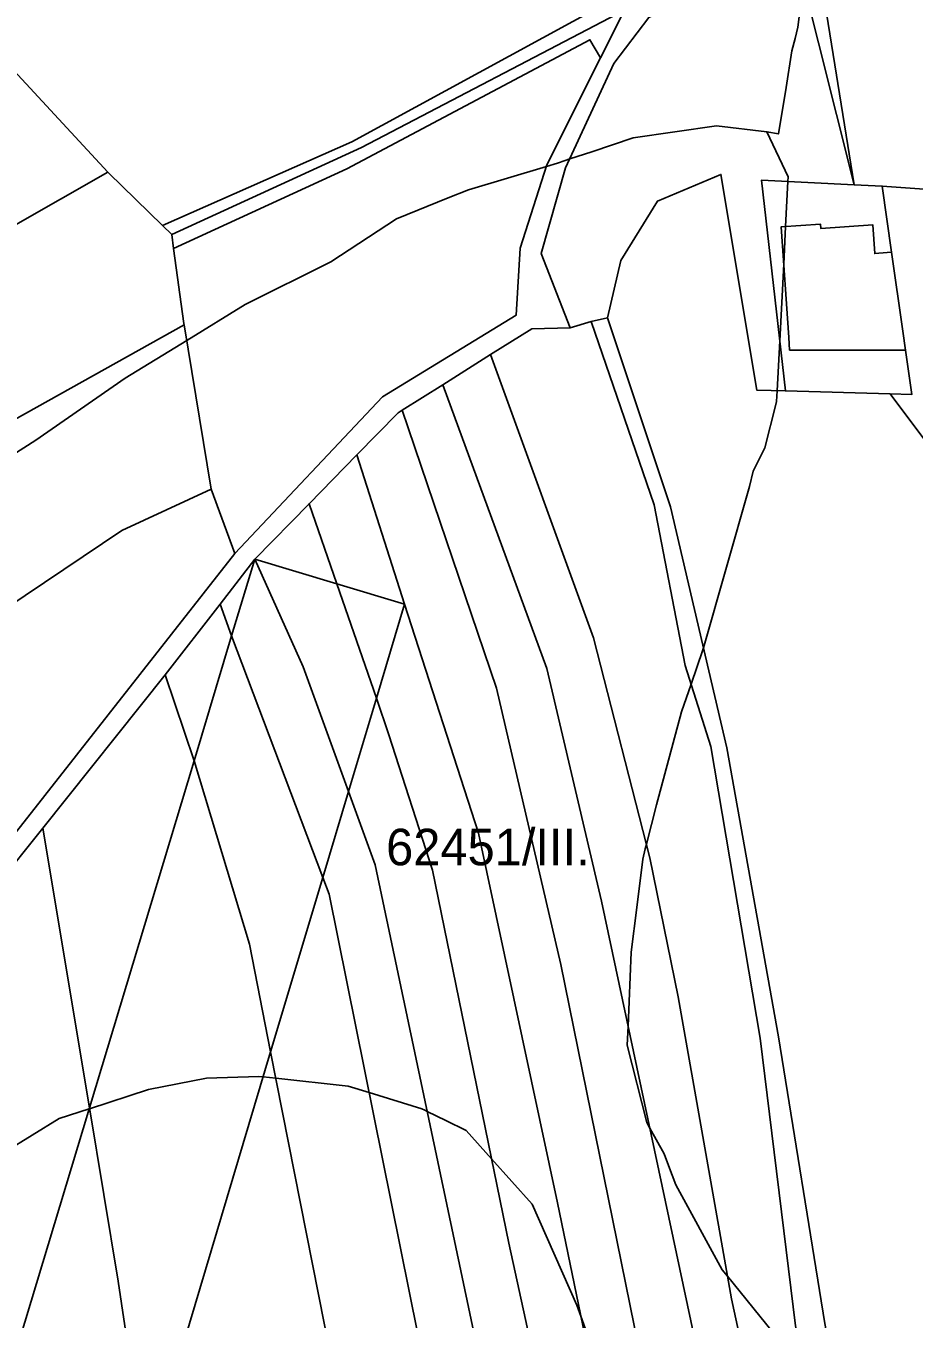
# Model space of a CAD drawing. Extents: x -502026 to -497664, y -1143484 to -1138019.
# Drawn here: x -499718.6 to -499523.9, y -1138993.9 to -1138710.6 of the extents above; entities that cross this region are included whole.
import ezdxf

# ---------------------------------------------------------------- set-up
doc = ezdxf.new("R2010")
doc.units = 0
for name, color, linetype in [('25', 7, 'Continuous'), ('31', 7, 'Continuous'), ('37', 7, 'Continuous'), ('43', 7, 'Continuous'), ('55', 7, 'Continuous'), ('62', 7, 'Continuous'), ('7', 7, 'Continuous')]:
    doc.layers.add(name, color=color, linetype=linetype)

msp = doc.modelspace()

# ---------------------------------------------------------------- linework, layer by layer
at = {"layer": '25'}
for points in [[(-499537.01, -1138745.37), (-499530.87, -1138745.67), (-499528.82, -1138760.16), (-499531.63, -1138760.38), (-499532.54, -1138760.45), (-499532.98, -1138754.15), (-499544.35, -1138754.93), (-499544.41, -1138754.03), (-499553.04, -1138754.62), (-499551.38, -1138778.83), (-499551.19, -1138781.59), (-499525.8, -1138781.59), (-499524.4, -1138791.35), (-499529.18, -1138791.22), (-499552.1, -1138790.55), (-499557.37, -1138744.4)], [(-499513.48, -1138746.91), (-499511.89, -1138808.1), (-499511.73, -1138814.39), (-499529.18, -1138791.22), (-499524.4, -1138791.35), (-499525.8, -1138781.59), (-499526.38, -1138777.45), (-499528.82, -1138760.16), (-499530.87, -1138745.67)]]:
    msp.add_lwpolyline(points, close=True, dxfattribs=at)
at = {"layer": '31'}
msp.add_lwpolyline([(-499537.01, -1138745.37), (-499557.37, -1138744.4), (-499552.1, -1138790.55), (-499558.38, -1138790.37), (-499566.24, -1138743.1), (-499580.14, -1138748.95), (-499588.16, -1138761.99), (-499591.11, -1138774.54), (-499594.7, -1138775.32), (-499599.24, -1138776.76), (-499605.61, -1138760.41), (-499600.27, -1138741.69), (-499589.7, -1138718.79), (-499582.04, -1138708.7), (-499568.17, -1138701.36), (-499548.75, -1138698.77)], close=True, dxfattribs=at)
at = {"layer": '37'}
msp.add_lwpolyline([(-499513.48, -1138746.91), (-499530.87, -1138745.67), (-499537.01, -1138745.37), (-499544.51, -1138699.06), (-499543.1, -1138676.2), (-499528.49, -1138637.04), (-499524.27, -1138622.83), (-499521.46, -1138603.68)], dxfattribs=at)
for points in [[(-499584.72, -1138701.93), (-499647.14, -1138735.95), (-499688.61, -1138754.3), (-499700.38, -1138742.85), (-499700.56, -1138742.65), (-499729.36, -1138711.56), (-499750.17, -1138715.52), (-499792.14, -1138739.41), (-499812.14, -1138754.89), (-499835.52, -1138777.51), (-499839.65, -1138763.23), (-499841.22, -1138736.39), (-499828.03, -1138721.09), (-499812.98, -1138708.74), (-499778.38, -1138690.2), (-499715.47, -1138666.65), (-499697.07, -1138662.14), (-499624.19, -1138623.47), (-499605.59, -1138653.48), (-499597.17, -1138655.53), (-499535.12, -1138622.58), (-499555.94, -1138687.68), (-499558.61, -1138690.15), (-499573.23, -1138697.97)], [(-499587.35, -1138707.16), (-499644.97, -1138737.18), (-499686.59, -1138756.26), (-499688.61, -1138754.3), (-499647.14, -1138735.95), (-499584.72, -1138701.93)], [(-499592.6, -1138717.6), (-499594.93, -1138713.6), (-499648.25, -1138741.88), (-499686.17, -1138759.35), (-499686.59, -1138756.26), (-499644.97, -1138737.18), (-499587.35, -1138707.16)], [(-499700.56, -1138742.65), (-499742.16, -1138766.28), (-499759.69, -1138777.83), (-499794.21, -1138803.47), (-499825.87, -1138829.77), (-499828.42, -1138802.06), (-499835.52, -1138777.51), (-499812.14, -1138754.89), (-499792.14, -1138739.41), (-499750.17, -1138715.52), (-499729.36, -1138711.56)], [(-499592.6, -1138717.6), (-499604.38, -1138741.01), (-499610.25, -1138759.27), (-499611.14, -1138773.96), (-499640.38, -1138791.84), (-499672.73, -1138826.19), (-499677.97, -1138812.1), (-499683.87, -1138776.05), (-499683.91, -1138775.8), (-499686.17, -1138759.35), (-499648.25, -1138741.88), (-499594.93, -1138713.6)], [(-499688.61, -1138754.3), (-499686.59, -1138756.26), (-499686.17, -1138759.35), (-499683.91, -1138775.8), (-499683.87, -1138776.05), (-499741.05, -1138807.99), (-499788.02, -1138846.17), (-499817.14, -1138873.87), (-499819.87, -1138875.19), (-499825.87, -1138829.77), (-499794.21, -1138803.47), (-499759.69, -1138777.83), (-499742.16, -1138766.28), (-499700.56, -1138742.65), (-499700.38, -1138742.85)], [(-499552.1, -1138790.55), (-499529.18, -1138791.22), (-499511.73, -1138814.39), (-499465.58, -1138874.76), (-499448.8, -1138941.59), (-499481.51, -1138993.07), (-499490.65, -1139028.16), (-499509.08, -1139023.11), (-499518.14, -1139024.19), (-499536.05, -1139033.29), (-499543.48, -1138994.87), (-499553.65, -1138932.11), (-499564.96, -1138868.79), (-499577.25, -1138815.93), (-499591.11, -1138774.54), (-499588.16, -1138761.99), (-499580.14, -1138748.95), (-499566.24, -1138743.1), (-499558.38, -1138790.37)], [(-499677.97, -1138812.1), (-499697.49, -1138821.17), (-499735.75, -1138846.76), (-499768.66, -1138874.79), (-499818.19, -1138913.08), (-499818.08, -1138888.78), (-499819.87, -1138875.19), (-499817.14, -1138873.87), (-499788.02, -1138846.17), (-499741.05, -1138807.99), (-499683.87, -1138776.05)], [(-499672.73, -1138826.19), (-499728.38, -1138896.85), (-499761.65, -1138926.83), (-499778.12, -1138948.42), (-499808.88, -1138958.63), (-499811.95, -1138942.47), (-499818.21, -1138917.28), (-499818.19, -1138913.08), (-499768.66, -1138874.79), (-499735.75, -1138846.76), (-499697.49, -1138821.17), (-499677.97, -1138812.1)], [(-499647.86, -1138878.32), (-499653.5, -1138897.19), (-499673.46, -1138844.21), (-499668.41, -1138827.44), (-499657.82, -1138850.99)], [(-499650.43, -1138832.83), (-499641.75, -1138857.88), (-499647.86, -1138878.32), (-499657.82, -1138850.99), (-499668.41, -1138827.44)], [(-499635.6, -1138837.28), (-499641.75, -1138857.88), (-499650.43, -1138832.83)], [(-499653.5, -1138897.19), (-499664.91, -1138935.38), (-499669.55, -1138911.75), (-499681.68, -1138871.58), (-499673.46, -1138844.21)], [(-499664.91, -1138935.38), (-499692.22, -1139026.74), (-499698.3, -1138985.62), (-499704.64, -1138947.61), (-499681.68, -1138871.58), (-499669.55, -1138911.75)], [(-499692.22, -1139026.74), (-499706.34, -1139073.94), (-499740.09, -1139074.1), (-499740.7, -1139066.99), (-499704.64, -1138947.61), (-499698.3, -1138985.62)]]:
    msp.add_lwpolyline(points, close=True, dxfattribs=at)
at = {"layer": '43'}
msp.add_lwpolyline([(-499537.01, -1138745.37), (-499548.75, -1138698.77), (-499546.8, -1138675.05), (-499544.76, -1138664.32), (-499536.74, -1138644.34), (-499529, -1138621.3), (-499527.08, -1138606.23), (-499515.85, -1138575.58), (-499509.34, -1138543.14), (-499505.39, -1138478.58), (-499500.91, -1138476.52), (-499503.34, -1138544.42), (-499509.59, -1138576.6), (-499521.46, -1138603.68), (-499524.27, -1138622.83), (-499528.49, -1138637.04), (-499543.1, -1138676.2), (-499544.51, -1138699.06)], close=True, dxfattribs=at)
at = {"layer": '55'}
for points in [[(-499728.38, -1138896.85), (-499672.73, -1138826.19), (-499640.38, -1138791.84), (-499611.14, -1138773.96), (-499610.25, -1138759.27), (-499604.38, -1138741.01), (-499592.6, -1138717.6), (-499587.35, -1138707.16)], [(-499582.04, -1138708.7), (-499589.7, -1138718.79), (-499600.27, -1138741.69), (-499605.61, -1138760.41), (-499599.24, -1138776.76), (-499607.64, -1138776.92), (-499616.74, -1138782.59), (-499627.2, -1138789.19), (-499636.08, -1138794.8), (-499637, -1138795.38), (-499646, -1138804.57), (-499656.5, -1138815.29), (-499668.41, -1138827.44), (-499675.99, -1138837.31), (-499688.06, -1138852.74), (-499714.87, -1138886.33), (-499725.1, -1138899.04)]]:
    msp.add_lwpolyline(points, dxfattribs=at)
for points in [[(-499528.82, -1138760.16), (-499526.38, -1138777.45), (-499525.8, -1138781.59), (-499551.19, -1138781.59), (-499551.38, -1138778.83), (-499553.04, -1138754.62), (-499544.41, -1138754.03), (-499544.35, -1138754.93), (-499532.98, -1138754.15), (-499532.54, -1138760.45), (-499531.63, -1138760.38)], [(-499536.05, -1139033.29), (-499534.62, -1139040.71), (-499533.7, -1139045.48), (-499567.38, -1139073.53), (-499568.33, -1139069.19), (-499558.8, -1139060.19), (-499550.32, -1139052.19), (-499539.22, -1139041.71), (-499549.88, -1138995.4), (-499557.61, -1138932.35), (-499568.42, -1138868.46), (-499574.1, -1138850.74), (-499580.84, -1138815.48), (-499594.7, -1138775.32), (-499591.11, -1138774.54), (-499577.25, -1138815.93), (-499564.96, -1138868.79), (-499553.65, -1138932.11), (-499543.48, -1138994.87)]]:
    msp.add_lwpolyline(points, close=True, dxfattribs=at)
at = {"layer": '62'}
for points in [[(-499548.53, -1138704), (-499549.37, -1138710.87), (-499549.99, -1138713.35), (-499550.66, -1138716), (-499551.97, -1138724.08), (-499553.62, -1138734.25), (-499556.16, -1138733.75), (-499567.22, -1138732.5), (-499585.5, -1138735.12), (-499594.55, -1138738.13), (-499599.36, -1138739.73), (-499600.39, -1138740.07), (-499602.06, -1138740.62), (-499604.49, -1138741.35), (-499621.59, -1138746.5), (-499625.98, -1138748.28), (-499637.31, -1138752.87), (-499651.75, -1138762.25), (-499670.47, -1138771.62), (-499683.31, -1138779.48), (-499696.81, -1138787.75), (-499716.34, -1138801.37), (-499743.09, -1138818.37)], [(-499554.91, -1138996.75), (-499564.83, -1138984.49), (-499565.94, -1138983.12), (-499576.12, -1138964.5), (-499577.73, -1138960.28), (-499578.69, -1138957.75), (-499581.82, -1138952.1), (-499582.5, -1138950.87), (-499586.75, -1138933.87), (-499586.58, -1138929.76), (-499585.91, -1138913.5), (-499584.7, -1138903.77), (-499583.37, -1138893.12), (-499582.81, -1138890.9), (-499582.55, -1138889.85), (-499580.37, -1138881.25), (-499574.87, -1138860.87), (-499572.79, -1138854.82), (-499570.19, -1138847.25), (-499570.07, -1138846.83), (-499560, -1138811.5), (-499559.16, -1138808.12), (-499557.57, -1138804.95), (-499556.59, -1138803), (-499554.19, -1138793.5), (-499554.03, -1138792.87), (-499553.91, -1138790.5), (-499553.35, -1138779.61), (-499552.48, -1138762.75), (-499552.06, -1138754.55), (-499551.55, -1138744.68), (-499551.5, -1138743.62), (-499556.16, -1138733.75), (-499553.62, -1138734.25), (-499551.97, -1138724.08), (-499550.66, -1138716), (-499549.99, -1138713.35), (-499549.37, -1138710.87), (-499548.53, -1138704)], [(-499743.09, -1138818.37), (-499716.34, -1138801.37), (-499696.81, -1138787.75), (-499683.31, -1138779.48), (-499670.47, -1138771.62), (-499651.75, -1138762.25), (-499637.31, -1138752.87), (-499625.98, -1138748.28), (-499621.59, -1138746.5), (-499604.49, -1138741.35), (-499602.06, -1138740.62), (-499600.39, -1138740.07), (-499599.36, -1138739.73), (-499594.55, -1138738.13), (-499585.5, -1138735.12), (-499567.22, -1138732.5), (-499556.16, -1138733.75), (-499551.5, -1138743.62), (-499551.55, -1138744.68), (-499552.06, -1138754.55), (-499552.48, -1138762.75), (-499553.35, -1138779.61), (-499553.91, -1138790.5), (-499554.03, -1138792.87), (-499554.19, -1138793.5), (-499556.59, -1138803), (-499557.57, -1138804.95), (-499559.16, -1138808.12), (-499560, -1138811.5), (-499570.07, -1138846.83), (-499570.19, -1138847.25), (-499572.79, -1138854.82), (-499574.87, -1138860.87), (-499580.37, -1138881.25), (-499582.55, -1138889.85), (-499582.81, -1138890.9), (-499583.37, -1138893.12), (-499584.7, -1138903.77), (-499585.91, -1138913.5), (-499586.58, -1138929.76), (-499586.75, -1138933.87), (-499582.5, -1138950.87), (-499581.82, -1138952.1), (-499578.69, -1138957.75), (-499577.73, -1138960.28), (-499576.12, -1138964.5), (-499565.94, -1138983.12), (-499564.83, -1138984.49), (-499554.91, -1138996.75)], [(-499723.12, -1138957.25), (-499711.25, -1138950), (-499704.72, -1138947.87), (-499704.6, -1138947.83), (-499691.69, -1138943.62), (-499678.97, -1138941.12), (-499667.47, -1138940.75), (-499666.55, -1138940.85), (-499663.77, -1138941.15), (-499647.94, -1138942.87), (-499643.35, -1138944.29), (-499631.78, -1138947.87), (-499631.16, -1138948.17), (-499630.61, -1138948.45), (-499626.54, -1138950.43), (-499622.03, -1138952.62), (-499616.51, -1138958.79), (-499607.59, -1138968.75), (-499597.81, -1138990.87), (-499596.96, -1138993.25), (-499583.78, -1139029.87)], [(-499583.78, -1139029.87), (-499596.96, -1138993.25), (-499597.81, -1138990.87), (-499607.59, -1138968.75), (-499616.51, -1138958.79), (-499622.03, -1138952.62), (-499626.54, -1138950.43), (-499630.61, -1138948.45), (-499631.16, -1138948.17), (-499631.78, -1138947.87), (-499643.35, -1138944.29), (-499647.94, -1138942.87), (-499663.77, -1138941.15), (-499666.55, -1138940.85), (-499667.47, -1138940.75), (-499678.97, -1138941.12), (-499691.69, -1138943.62), (-499704.6, -1138947.83), (-499704.72, -1138947.87), (-499711.25, -1138950), (-499723.12, -1138957.25)]]:
    msp.add_lwpolyline(points, dxfattribs=at)
at = {"layer": '7'}
for points in [[(-499550.32, -1139052.19), (-499563.95, -1138989.48), (-499575.62, -1138923.31), (-499581.78, -1138892.84), (-499594.17, -1138844.68), (-499616.74, -1138782.59), (-499607.64, -1138776.92), (-499599.24, -1138776.76), (-499594.7, -1138775.32), (-499580.84, -1138815.48), (-499574.1, -1138850.74), (-499568.42, -1138868.46), (-499557.61, -1138932.35), (-499549.88, -1138995.4), (-499539.22, -1139041.71)], [(-499550.32, -1139052.19), (-499558.8, -1139060.19), (-499592.41, -1138902.38), (-499604.4, -1138851.39), (-499627.2, -1138789.19), (-499616.74, -1138782.59), (-499594.17, -1138844.68), (-499581.78, -1138892.84), (-499575.62, -1138923.31), (-499563.95, -1138989.48)], [(-499558.8, -1139060.19), (-499568.33, -1139069.19), (-499570.98, -1139071.69), (-499581.43, -1139014.02), (-499601.29, -1138916.25), (-499615.44, -1138855.68), (-499636.08, -1138794.8), (-499627.2, -1138789.19), (-499604.4, -1138851.39), (-499592.41, -1138902.38)], [(-499570.98, -1139071.69), (-499575.22, -1139075.69), (-499579.95, -1139075.59), (-499602.08, -1138968.45), (-499619.35, -1138887.46), (-499635.6, -1138837.28), (-499646, -1138804.57), (-499637, -1138795.38), (-499636.08, -1138794.8), (-499615.44, -1138855.68), (-499601.29, -1138916.25), (-499581.43, -1139014.02)], [(-499635.6, -1138837.28), (-499650.43, -1138832.83), (-499656.5, -1138815.29), (-499646, -1138804.57)], [(-499650.43, -1138832.83), (-499668.41, -1138827.44), (-499656.5, -1138815.29)], [(-499673.46, -1138844.21), (-499675.99, -1138837.31), (-499668.41, -1138827.44)], [(-499673.46, -1138844.21), (-499681.68, -1138871.58), (-499688.06, -1138852.74), (-499675.99, -1138837.31)], [(-499579.95, -1139075.59), (-499591.31, -1139075.34), (-499612.72, -1138977.31), (-499629.44, -1138895.59), (-499638.98, -1138865.88), (-499641.75, -1138857.88), (-499635.6, -1138837.28), (-499619.35, -1138887.46), (-499602.08, -1138968.45)], [(-499681.68, -1138871.58), (-499704.64, -1138947.61), (-499714.87, -1138886.33), (-499688.06, -1138852.74)], [(-499591.31, -1139075.34), (-499603.91, -1139075.07), (-499642, -1138894.4), (-499647.86, -1138878.32), (-499641.75, -1138857.88), (-499638.98, -1138865.88), (-499629.44, -1138895.59), (-499612.72, -1138977.31)], [(-499603.91, -1139075.07), (-499617.01, -1139074.78), (-499652.12, -1138900.84), (-499653.5, -1138897.19), (-499647.86, -1138878.32), (-499642, -1138894.4)], [(-499704.64, -1138947.61), (-499740.7, -1139066.99), (-499744.7, -1139019.96), (-499758.97, -1138930.35), (-499725.1, -1138899.04), (-499714.87, -1138886.33)], [(-499617.01, -1139074.78), (-499637.37, -1139074.58), (-499664.91, -1138935.38), (-499653.5, -1138897.19), (-499652.12, -1138900.84)], [(-499637.37, -1139074.58), (-499685.33, -1139074.11), (-499692.22, -1139026.74), (-499664.91, -1138935.38)]]:
    msp.add_lwpolyline(points, close=True, dxfattribs=at)

# ---------------------------------------------------------------- texts
at = {"layer": '62'}
msp.add_text('62451/III.', height=8, dxfattribs=at).set_placement((-499639.61, -1138894.49))

doc.saveas('drawing.dxf')
